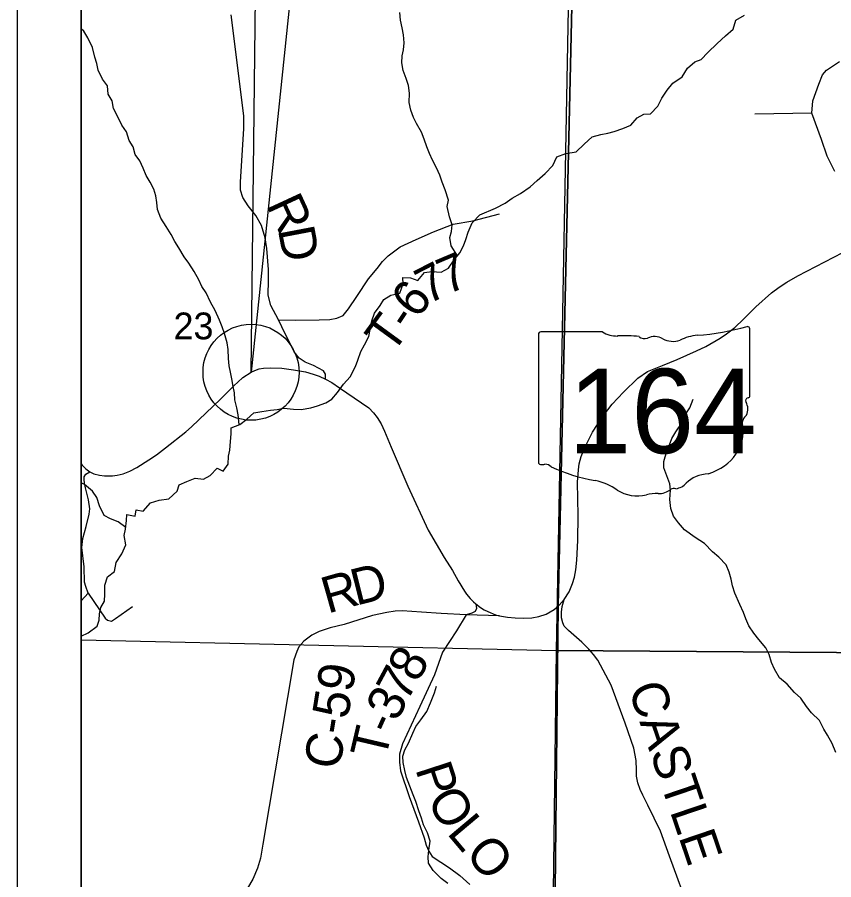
# Model space of a CAD drawing. Extents: x -20.5 to 34, y -66 to 23.9.
# Drawn here: x 2 to 3.275, y 15.05 to 16.397 of the extents above; entities that cross this region are included whole.
import ezdxf

# ---------------------------------------------------------------- set-up
doc = ezdxf.new("R2010")
doc.units = 0
for name, color, linetype in [('Default', 7, 'Continuous'), ('GM_X_County_Text', 7, 'Continuous'), ('GM_X_Minor_Lake', 7, 'Continuous'), ('GM_X_Minor_River_Text', 7, 'Continuous'), ('GM_X_Section_Text', 7, 'Continuous'), ('GM_X_State_Route', 7, 'Continuous'), ('GM_X_Township_Road', 7, 'Continuous'), ('GM_X_Township_Road_Text', 7, 'Continuous'), ('GM_X_Township_Text', 7, 'Continuous'), ('GM_X_Unincorporated', 7, 'Continuous'), ('GM_X_Unincorporated_Location', 7, 'Continuous'), ('SH_Cut_Line', 7, 'Continuous'), ('SH_Data', 7, 'Continuous'), ('SH_Text', 7, 'Continuous')]:
    doc.layers.add(name, color=color, linetype=linetype)

msp = doc.modelspace()

# ---------------------------------------------------------------- linework, layer by layer
at = {"layer": 'Default'}
for points in [[(2.1, 20.9), (8.9, 20.9), (8.9, 14.1), (2.1, 14.1)], [(2.1, 16.4424), (2.1, 15.425), (2.8417, 15.4083), (2.8609, 16.4392)]]:
    msp.add_lwpolyline(points, close=True, dxfattribs=at)
for points in [[(2.88, 18.0245), (2.8801, 18.0269), (2.8826, 18.5075), (2.8861, 18.9025), (2.8866, 19.0123), (2.1138, 19.0238), (2.1, 19.024), (2.1, 14.4131), (2.1154, 14.4129), (2.8202, 14.4012), (2.823, 14.4012), (2.8374, 14.7884), (2.8447, 15.4785), (2.8665, 16.4374), (2.8739, 17.2409)], [(2.8739, 17.2409), (2.8665, 16.4374), (2.8447, 15.4785), (2.8374, 14.7884)]]:
    msp.add_lwpolyline(points, dxfattribs=at)
at = {"layer": 'GM_X_County_Text'}
msp.add_line((3.2405, 16.2475), (3.1515, 16.246), dxfattribs=at)
for points in [[(2.4813, 15.8322), (2.4813, 15.8396), (2.478, 15.8451), (2.4627, 15.8534), (2.4494, 15.8586), (2.4399, 15.8647), (2.4325, 15.8745), (2.4248, 15.8899), (2.4182, 15.9026), (2.4081, 15.9248), (2.3961, 15.9468), (2.3917, 15.9633), (2.3922, 15.9865), (2.3923, 16.0033), (2.3895, 16.0359), (2.3871, 16.0528), (2.3812, 16.0718), (2.3725, 16.0877), (2.3607, 16.1025), (2.352, 16.1159), (2.3483, 16.1272), (2.3483, 16.1394), (2.3538, 16.2236), (2.3536, 16.2435), (2.3337, 16.4008)], [(3.2765, 16.1565), (3.2643, 16.1803), (3.2554, 16.2065), (3.2405, 16.2475), (3.2418, 16.2666), (3.2513, 16.2927), (3.2571, 16.3072), (3.2635, 16.3144), (3.2839, 16.3283)], [(2.4081, 15.9248), (2.4337, 15.9242), (2.4713, 15.9247), (2.4879, 15.9252), (2.4989, 15.9273), (2.5089, 15.9315), (2.517, 15.9418), (2.5302, 15.961), (2.5483, 15.9886), (2.562, 16.0047), (2.5702, 16.0159), (2.5737, 16.0194), (2.5773, 16.0229), (2.5792, 16.0246), (2.598, 16.0385), (2.6227, 16.05), (2.65, 16.0621), (2.6805, 16.0742), (2.7111, 16.0793), (2.7529, 16.09)], [(2.1, 15.4858), (2.1106, 15.4978), (2.1073, 15.5083), (2.1051, 15.5151), (2.1043, 15.5391), (2.1008, 15.569), (2.1023, 15.5833), (2.1074, 15.602), (2.1123, 15.6213), (2.1133, 15.6293), (2.1114, 15.6437), (2.1065, 15.6623), (2.1051, 15.6698), (2.1047, 15.6753), (2.1047, 15.6796), (2.1069, 15.6834), (2.1134, 15.6873)], [(2.1106, 15.4978), (2.1371, 15.4586), (2.141, 15.4555), (2.1472, 15.4541), (2.1533, 15.4583), (2.1799, 15.4768)], [(2.7158, 15.4813), (2.7169, 15.4736), (2.715, 15.4693), (2.7097, 15.4664), (2.7007, 15.4638), (2.6858, 15.4392), (2.6641, 15.4058), (2.6516, 15.3704), (2.6286, 15.3207), (2.6016, 15.2626), (2.597, 15.2465), (2.5968, 15.2337), (2.5983, 15.2205), (2.6116, 15.1803), (2.6262, 15.1406), (2.635, 15.1155), (2.6384, 15.104), (2.6424, 15.0948), (2.648, 15.0868), (2.6746, 15.0686), (2.6908, 15.0567), (2.7066, 15.0429)]]:
    msp.add_lwpolyline(points, dxfattribs=at)
at = {"layer": 'GM_X_Minor_Lake'}
msp.add_lwpolyline([(3.8817, 16.4153), (3.8622, 15.401), (2.8417, 15.4083), (2.8609, 16.4392)], close=True, dxfattribs=at)
msp.add_lwpolyline([(3.8345, 14.5564), (3.829, 14.3877), (2.8293, 14.4033), (2.8417, 15.4083), (3.8622, 15.401), (3.8602, 15.34)], dxfattribs=at)
at = {"layer": 'GM_X_Minor_River_Text'}
for points in [[(2.6871, 16.0245), (2.6773, 16.0401), (2.6752, 16.053), (2.6777, 16.0625), (2.679, 16.0731), (2.6746, 16.0856), (2.671, 16.1018), (2.6731, 16.1113), (2.6682, 16.1279), (2.6635, 16.1396), (2.6595, 16.1505), (2.6544, 16.1618), (2.6481, 16.1742), (2.6434, 16.1844), (2.6395, 16.1946), (2.6351, 16.2066), (2.6311, 16.2175), (2.6233, 16.2311), (2.6186, 16.2408), (2.6143, 16.2521), (2.6118, 16.2639), (2.6123, 16.2787), (2.611, 16.2908), (2.607, 16.3017), (2.6026, 16.3138), (2.6005, 16.3258), (2.6011, 16.3369), (2.6032, 16.3464), (2.6042, 16.357), (2.6032, 16.3699), (2.6007, 16.3808), (2.5982, 16.3929), (2.5973, 16.4047)], [(2.7038, 16.0614), (2.7104, 16.0759), (2.7223, 16.0886), (2.7467, 16.0989), (2.7617, 16.1068), (2.7726, 16.1145), (2.7857, 16.122), (2.8007, 16.1325), (2.8118, 16.1421), (2.8242, 16.1533), (2.8361, 16.1657), (2.8423, 16.1791), (2.8566, 16.1846), (2.8724, 16.1868), (2.8851, 16.1988), (2.8974, 16.2103), (2.9113, 16.214), (2.9219, 16.2164), (2.9321, 16.2189), (2.9456, 16.2233), (2.958, 16.2288), (2.968, 16.24), (2.9782, 16.2459), (2.9884, 16.2464), (2.9999, 16.2584), (3.0061, 16.271), (3.0146, 16.2833), (3.0235, 16.2944), (3.0381, 16.3041), (3.0466, 16.3176), (3.0578, 16.3276), (3.0676, 16.3312), (3.078, 16.3424), (3.0925, 16.3563), (3.1056, 16.3682), (3.1175, 16.3787), (3.1218, 16.3924), (3.1353, 16.4006)], [(2.3465, 15.761), (2.3448, 15.7765), (2.3428, 15.7871), (2.3395, 15.7996), (2.339, 15.8106), (2.3369, 15.8204), (2.3352, 15.8325), (2.3327, 15.8431), (2.3307, 15.8529), (2.3297, 15.8643), (2.3291, 15.8783), (2.3278, 15.8885), (2.3238, 15.9032), (2.3198, 15.9138), (2.3158, 15.9239), (2.3088, 15.9394), (2.3017, 15.9521), (2.2947, 15.9668), (2.2881, 15.9766), (2.2834, 15.9871), (2.2763, 16.0003), (2.2678, 16.0134), (2.2608, 16.0231), (2.2522, 16.037), (2.246, 16.0472), (2.2401, 16.058), (2.2324, 16.0704), (2.2242, 16.0836), (2.2187, 16.0971), (2.2177, 16.1077), (2.2164, 16.1183), (2.2132, 16.1285), (2.2073, 16.1398), (2.2015, 16.1499), (2.1964, 16.1616), (2.1916, 16.1729), (2.1843, 16.183), (2.1807, 16.1947), (2.1748, 16.2045), (2.1704, 16.2184), (2.1634, 16.2285), (2.1587, 16.2387), (2.1505, 16.2545), (2.148, 16.2666), (2.1418, 16.2771), (2.1408, 16.29), (2.1331, 16.3004), (2.1264, 16.3147), (2.1243, 16.3249), (2.1211, 16.3347), (2.1175, 16.3499), (2.1104, 16.3653), (2.1041, 16.3754), (2.1, 16.3792)], [(2.1, 15.4305), (2.1109, 15.4361), (2.1248, 15.4462), (2.128, 15.4557), (2.1286, 15.4656), (2.1303, 15.4755), (2.1362, 15.4854), (2.1368, 15.4964), (2.1369, 15.5101), (2.1409, 15.5235), (2.1517, 15.5316), (2.1545, 15.5457), (2.1634, 15.5591), (2.1696, 15.5733), (2.1671, 15.5876), (2.1692, 15.5979), (2.1705, 15.6112), (2.171, 15.6207), (2.184, 15.6183), (2.1857, 15.6278), (2.1967, 15.6257), (2.2078, 15.6388), (2.2218, 15.6432), (2.2365, 15.6449), (2.2496, 15.6569), (2.2528, 15.6668), (2.2648, 15.672), (2.278, 15.6775), (2.2909, 15.6758), (2.3014, 15.6817), (2.3122, 15.6929), (2.3217, 15.6885), (2.3295, 15.6993), (2.3296, 15.7118), (2.3321, 15.7213), (2.333, 15.7346), (2.334, 15.7464), (2.3342, 15.7558), (2.3474, 15.7614), (2.3582, 15.7695), (2.3694, 15.7792), (2.3818, 15.7813), (2.3951, 15.7834), (2.4056, 15.7844), (2.4162, 15.7865), (2.4314, 15.7852), (2.4431, 15.7846), (2.4582, 15.7872), (2.4688, 15.7904), (2.4816, 15.7952), (2.4913, 15.8006), (2.4998, 15.811), (2.5095, 15.8241), (2.5195, 15.8356), (2.5279, 15.8517), (2.5319, 15.8616), (2.5362, 15.8754), (2.5421, 15.8857), (2.5487, 15.8987), (2.5508, 15.9094), (2.5536, 15.9231), (2.5579, 15.9349), (2.5664, 15.9468), (2.5723, 15.9564), (2.5832, 15.963), (2.5972, 15.9663), (2.6026, 15.9808), (2.6017, 15.991), (2.6138, 15.9901), (2.6252, 15.9861), (2.636, 15.9988), (2.6473, 16.0001), (2.6617, 15.9989), (2.6733, 16.0051), (2.6822, 16.0186), (2.6911, 16.0293), (2.6966, 16.0404), (2.7002, 16.05), (2.7038, 16.0614)], [(3.278, 15.2491), (3.2721, 15.2631), (3.2651, 15.2759), (3.2593, 15.2856), (3.2522, 15.2988), (3.2399, 15.3111), (3.2322, 15.3208), (3.2233, 15.3336), (3.2136, 15.3429), (3.2021, 15.3556), (3.1902, 15.3656), (3.182, 15.3792), (3.1777, 15.3897), (3.1737, 15.4018), (3.1686, 15.4123), (3.1578, 15.4254), (3.1497, 15.4352), (3.1423, 15.4468), (3.1375, 15.4577), (3.134, 15.4675), (3.1281, 15.4803), (3.1202, 15.498), (3.1166, 15.5093), (3.1146, 15.5195), (3.1113, 15.5305), (3.1066, 15.5418), (3.0951, 15.5541), (3.0855, 15.5623), (3.0727, 15.5754), (3.0582, 15.5846), (3.0417, 15.5968), (3.0321, 15.6077), (3.0243, 15.6178), (3.0203, 15.6299), (3.0186, 15.6442), (3.0199, 15.6587), (3.0189, 15.6685), (3.0094, 15.6934), (3.0093, 15.7033), (3.0139, 15.7197), (3.0183, 15.7296), (3.0219, 15.7395), (3.0282, 15.7499), (3.037, 15.7629), (3.0429, 15.7763), (3.0499, 15.787), (3.055, 15.8008)], [(2.1694, 15.6006), (2.1576, 15.6091), (2.1454, 15.6138), (2.1359, 15.619), (2.1284, 15.634), (2.1244, 15.6472), (2.1174, 15.6573), (2.1052, 15.6674), (2.1, 15.6701)], [(2.672, 15.0442), (2.6617, 15.0523), (2.6494, 15.0647), (2.642, 15.0763), (2.6414, 15.0862), (2.6424, 15.0964), (2.6448, 15.1105), (2.6404, 15.1233), (2.6342, 15.1361), (2.6313, 15.1463), (2.627, 15.1576), (2.6222, 15.1723), (2.6179, 15.1829), (2.6131, 15.1965), (2.6079, 15.2097), (2.6051, 15.2206), (2.6026, 15.2335), (2.6021, 15.2433), (2.6053, 15.2532), (2.6108, 15.2636), (2.6174, 15.2789), (2.6221, 15.2896), (2.6303, 15.3), (2.6392, 15.313), (2.645, 15.3264), (2.6512, 15.342), (2.6544, 15.3527)]]:
    msp.add_lwpolyline(points, dxfattribs=at)
at = {"layer": 'GM_X_State_Route'}
for points in [[(2.8499, 15.4679), (2.8509, 15.4768), (2.8537, 15.4878)], [(2.7529, 15.4624), (2.7007, 15.4638), (2.662, 15.4658), (2.631, 15.4679), (2.6009, 15.47), (2.59, 15.4695), (2.5772, 15.4677), (2.5545, 15.4627), (2.5103, 15.4488), (2.4885, 15.4434), (2.4715, 15.4377), (2.4599, 15.4323), (2.4473, 15.4227), (2.4397, 15.414), (2.4364, 15.4067), (2.4318, 15.3938), (2.3836, 15.1059), (2.3799, 15.0841), (2.375, 15.0685), (2.3677, 15.0513), (2.3594, 15.0371)], [(3.0509, 14.9976), (3.0183, 15.0873), (3.0044, 15.1262), (2.9843, 15.1667), (2.9768, 15.1821), (2.9726, 15.1913), (2.969, 15.2015), (2.9669, 15.2118), (2.9668, 15.2214), (2.966, 15.2363), (2.9626, 15.2559), (2.9492, 15.2949), (2.9272, 15.354), (2.9062, 15.3929), (2.8997, 15.4019), (2.8921, 15.4105), (2.8812, 15.4212), (2.8607, 15.4393), (2.8539, 15.4465), (2.8515, 15.4514), (2.8498, 15.4591), (2.8497, 15.4659), (2.8499, 15.4679)]]:
    msp.add_lwpolyline(points, dxfattribs=at)
at = {"layer": 'GM_X_Township_Road'}
msp.add_lwpolyline([(2.1, 15.6997), (2.1014, 15.6979), (2.1072, 15.692), (2.1134, 15.6873), (2.1198, 15.6843), (2.1286, 15.6821), (2.136, 15.6811), (2.1408, 15.6809), (2.1488, 15.6811), (2.156, 15.6819), (2.1654, 15.6844), (2.1757, 15.6884), (2.1869, 15.694), (2.2053, 15.7058), (2.2173, 15.7138), (2.2313, 15.7248), (2.2631, 15.7496), (2.2721, 15.7574), (2.3171, 15.8007), (2.3385, 15.8222), (2.3443, 15.8274), (2.3524, 15.8346), (2.365, 15.8428), (2.3711, 15.8456), (2.3776, 15.8479), (2.3845, 15.8491), (2.3957, 15.8496), (2.4132, 15.8491), (2.4312, 15.8467), (2.4502, 15.8433), (2.4622, 15.8399), (2.4715, 15.8366), (2.4813, 15.8322), (2.4909, 15.8266), (2.5033, 15.8183), (2.5487, 15.7872), (2.5562, 15.7796), (2.5619, 15.7721), (2.5679, 15.7624), (2.5735, 15.7508), (2.5839, 15.726), (2.6095, 15.6649), (2.6417, 15.5964), (2.6665, 15.5536), (2.6793, 15.533), (2.6885, 15.5171), (2.6982, 15.501), (2.7014, 15.4963), (2.7072, 15.4895), (2.7122, 15.4844), (2.7158, 15.4813), (2.7232, 15.4755), (2.7287, 15.472), (2.7346, 15.4689), (2.7464, 15.4641), (2.7529, 15.4624), (2.7655, 15.4605), (2.7772, 15.4594), (2.7907, 15.4588), (2.8033, 15.4593), (2.8145, 15.4613), (2.8255, 15.4652), (2.8384, 15.4725), (2.8449, 15.478), (2.8459, 15.4788), (2.8537, 15.4878), (2.8615, 15.4997), (2.867, 15.513), (2.87, 15.5226), (2.8722, 15.5343), (2.8734, 15.5493), (2.8752, 15.5799), (2.8755, 15.6189), (2.8746, 15.6713), (2.876, 15.6906), (2.8774, 15.6996), (2.8805, 15.7113), (2.8864, 15.7264), (2.8982, 15.7494), (2.9137, 15.7733), (2.929, 15.7929), (2.9466, 15.8118), (2.9689, 15.8337), (2.9841, 15.8438), (3.0071, 15.8533), (3.0303, 15.8629), (3.0605, 15.876), (3.0752, 15.8829), (3.0975, 15.8958), (3.1075, 15.9027), (3.1202, 15.9129), (3.1339, 15.9257), (3.1529, 15.9448), (3.1776, 15.9667), (3.1895, 15.9756), (3.2014, 15.9834), (3.2186, 15.9933), (3.3168, 16.0442)], dxfattribs=at)
at = {"layer": 'GM_X_Unincorporated'}
for p, q in [((3.1435, 15.8061), (3.1435, 15.9108)), ((2.8139, 15.9024), (2.8139, 15.7023)), ((2.9137, 15.9058), (2.8172, 15.9058)), ((3.1435, 15.8061), (3.1435, 15.8061))]:
    msp.add_line(p, q, dxfattribs=at)
for centre, major_axis, start_param, end_param in [((3.0261, 16.1786), (0.3495, 0), 4.814394, 5.042369), ((3.1398, 15.9112), (0.00367, 0), 6.141152, 7.989035), ((2.8177, 15.9028), (0.00382, 0), 1.712693, 3.28349), ((2.9367, 15.929), (0.037, 0), 4.042523, 4.731795), ((2.9489, 15.7935), (0.133, 0), 1.404758, 1.657858), ((2.9791, 15.9038), (0.0107, 0), 3.836095, 5.185415), ((2.9948, 15.8807), (0.0222, 0), 0.950623, 2.079405), ((3.0235, 15.9124), (0.0267, 0), 4.081561, 5.145723), ((3.0707, 15.8447), (0.0703, 0), 1.699011, 2.107814), ((3.1426, 15.7984), (0.00568, 0), 1.883978, 3.671073), ((3.1396, 15.8057), (0.00393, 0), 5.05454, 6.418171), ((3.1065, 15.7852), (0.0341, 0), 5.934695, 6.695948), ((3.1566, 15.7623), (0.0248, 0), 2.387724, 3.262537), ((3.0457, 15.749), (0.0874, 0), 5.101752, 6.440018), ((2.8177, 15.7018), (0.00385, 0), 3.00124, 4.508301), ((2.8183, 15.7223), (0.0294, 0), 4.665946, 4.897461), ((2.8243, 15.6907), (0.0106, 0), 0.519207, 1.627899), ((2.9581, 15.8705), (0.2524, 0), 4.195997, 4.488961), ((3.0825, 15.6461), (0.0479, 0), 1.647645, 2.488434), ((2.8829, 15.6123), (0.079, 0), 0.823519, 1.323587), ((3.0219, 15.6829), (0.0282, 0), 4.937069, 5.64225), ((2.9683, 15.6897), (0.0501, 0), 4.026481, 4.996735), ((2.9973, 15.6205), (0.0412, 0), 1.495662, 1.94098), ((3.0009, 15.6747), (0.0267, 0), 4.691044, 5.507374), ((3.0251, 15.6553), (0.00752, 0), 1.147584, 2.315152)]:
    msp.add_ellipse(centre, major_axis=major_axis, ratio=0.8, start_param=start_param, end_param=end_param, dxfattribs=at)
at = {"layer": 'SH_Cut_Line'}
msp.add_lwpolyline([(8.0662, 14.9881), (8.0784, 15.8902), (8.0825, 16.3121), (8.087, 16.6605), (8.0955, 17.3258), (8.2289, 17.3235), (8.271, 17.3227), (8.5216, 17.3182), (8.9, 17.3115), (8.9, 20.9), (2.1, 20.9), (2.1, 14.4131)], dxfattribs=at)
at = {"layer": 'SH_Data'}
for p, q in [((2, 21), (2, 14)), ((2.1, 20.9), (2.1, 14.1))]:
    msp.add_line(p, q, dxfattribs=at)
at = {"layer": 'SH_Text'}
msp.add_lwpolyline([(2.365, 15.8428), (2.3813, 17.2409), (2.5107, 17.2409)], close=True, dxfattribs=at)
msp.add_circle((2.365, 15.8428), 0.075, dxfattribs=at)

# ---------------------------------------------------------------- texts
at = {"layer": 'GM_X_Section_Text'}
for s, rotation, p in [('R', 294.8324, (2.3882, 16.1045)), ('D', 280.7841, (2.4067, 16.0657)), ('7', 22.9786, (2.6708, 15.9635)), ('7', 27.3168, (2.6407, 15.9479)), ('6', 52.07, (2.6242, 15.9244)), ('T', 53.8998, (2.5853, 15.8692)), ('-', 56.4921, (2.612, 15.9059)), ('8', 59.9493, (2.6241, 15.3562)), ('7', 61.7272, (2.6079, 15.326)), ('3', 63.8192, (2.5928, 15.2953)), ('-', 65.6875, (2.5835, 15.2747)), ('T', 76.77, (2.5747, 15.2361)), ('P', 288.0285, (2.6211, 15.2233)), ('O', 299.9514, (2.6382, 15.1751)), ('L', 310.0715, (2.6695, 15.1228)), ('O', 310.9275, (2.6974, 15.0896))]:
    msp.add_text(s, height=0.0568, rotation=rotation, dxfattribs=at).set_placement(p)
at = {"layer": 'GM_X_Township_Road_Text'}
for s, height, rotation, p in [('R', 0.0568, 15.8379, (2.4845, 15.4656)), ('D', 0.0568, 14.0769, (2.5289, 15.4782)), ('C-59', 0.05682, 80.7079, (2.5031, 15.2207)), ('CASTLE', 0.05682, 288.7732, (2.9533, 15.3493))]:
    msp.add_text(s, height=height, rotation=rotation, dxfattribs=at).set_placement(p)
at = {"layer": 'GM_X_Township_Text'}
msp.add_text('23', height=0.04186, rotation=0, dxfattribs=at).set_placement((2.244, 15.8942))
at = {"layer": 'GM_X_Unincorporated'}
msp.add_text('164', height=0.13184, dxfattribs=at).set_placement((2.8604, 15.7164))
at = {"layer": 'GM_X_Unincorporated_Location'}
for s in ['s', 'r']:
    msp.add_text(s, height=0.000189, dxfattribs=at).set_placement((2.975, 15.789))
msp.add_text('164', height=0.000189, rotation=0, dxfattribs=at).set_placement((2.9081, 15.7752))

doc.saveas('drawing.dxf')
